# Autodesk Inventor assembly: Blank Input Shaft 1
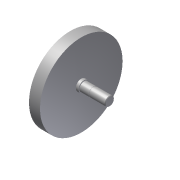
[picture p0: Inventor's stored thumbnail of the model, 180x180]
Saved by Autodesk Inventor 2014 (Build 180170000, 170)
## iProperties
Created: 2011-01
Part Number: Blank Input Shaft 1
Document SubType Name: Assembly
Designer: Beta-8540w
ClientObjectVersion: 1
Author: Beta-8540w
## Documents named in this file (2)
- C:\Inventor 2014 Essentials\Assemblies\Chapter 09\Design Accelerators\Blank Input Shaft 1.iam
- C:\Inventor 2014 Essentials\Assemblies\Chapter 09\Design Accelerators\Blank Input Shaft 1.ipt
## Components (1 placed, 1 different names)
1. Blank Input Shaft 1:1
